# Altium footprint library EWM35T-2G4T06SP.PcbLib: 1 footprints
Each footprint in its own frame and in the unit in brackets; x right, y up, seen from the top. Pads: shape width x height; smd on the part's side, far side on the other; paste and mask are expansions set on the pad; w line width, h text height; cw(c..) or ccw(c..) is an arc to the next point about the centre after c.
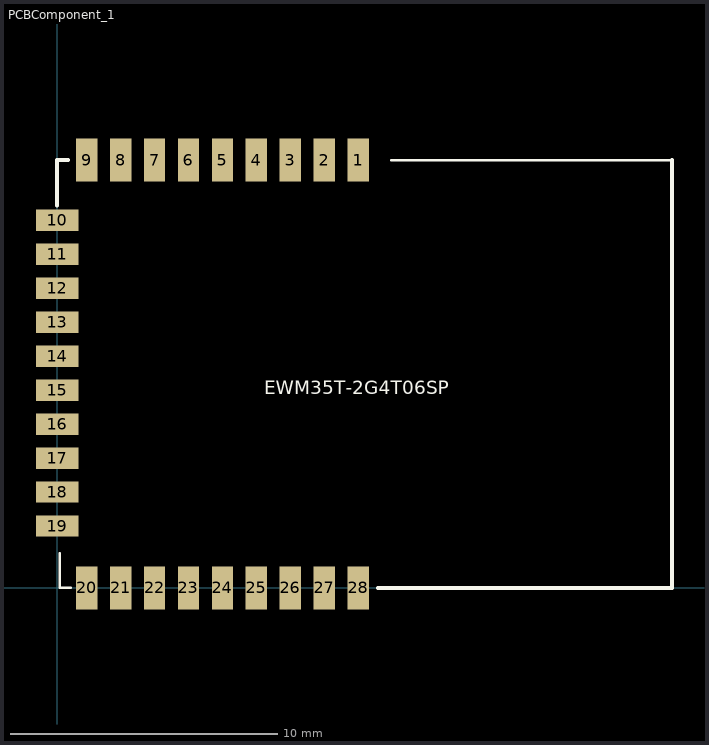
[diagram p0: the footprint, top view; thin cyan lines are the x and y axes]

## PCBComponent_1 [mm]
pads (28):
  rect 0.8x1.6 smd: 1(11.26,16) 2(9.99,16) 3(8.72,16) 4(7.45,16) 5(6.18,16) 6(4.91,16) 7(3.64,16) 8(2.37,16) 9(1.1,16) 20(1.1,0) 21(2.37,0) 22(3.64,0) 23(4.91,0) 24(6.18,0) 25(7.45,0) 26(8.72,0) 27(9.99,0) 28(11.26,0)
  rect 1.6x0.8 smd: 10(0,13.745) 11(0,12.475) 12(0,11.205) 13(0,9.935) 14(0,8.665) 15(0,7.395) 16(0,6.125) 17(0,4.855) 18(0,3.585) 19(0,2.315)
Top Overlay:
  lines w0.1: 0.1,1.3 0.1,0 0.5,0 ; 12.5,16 23,16
  lines w0.152: 0,14.3 0,16 0.4,16 ; 12,0 23,0 23,16
  text "EWM35T-2G4T06SP" at 7.735,7.25 h0.5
